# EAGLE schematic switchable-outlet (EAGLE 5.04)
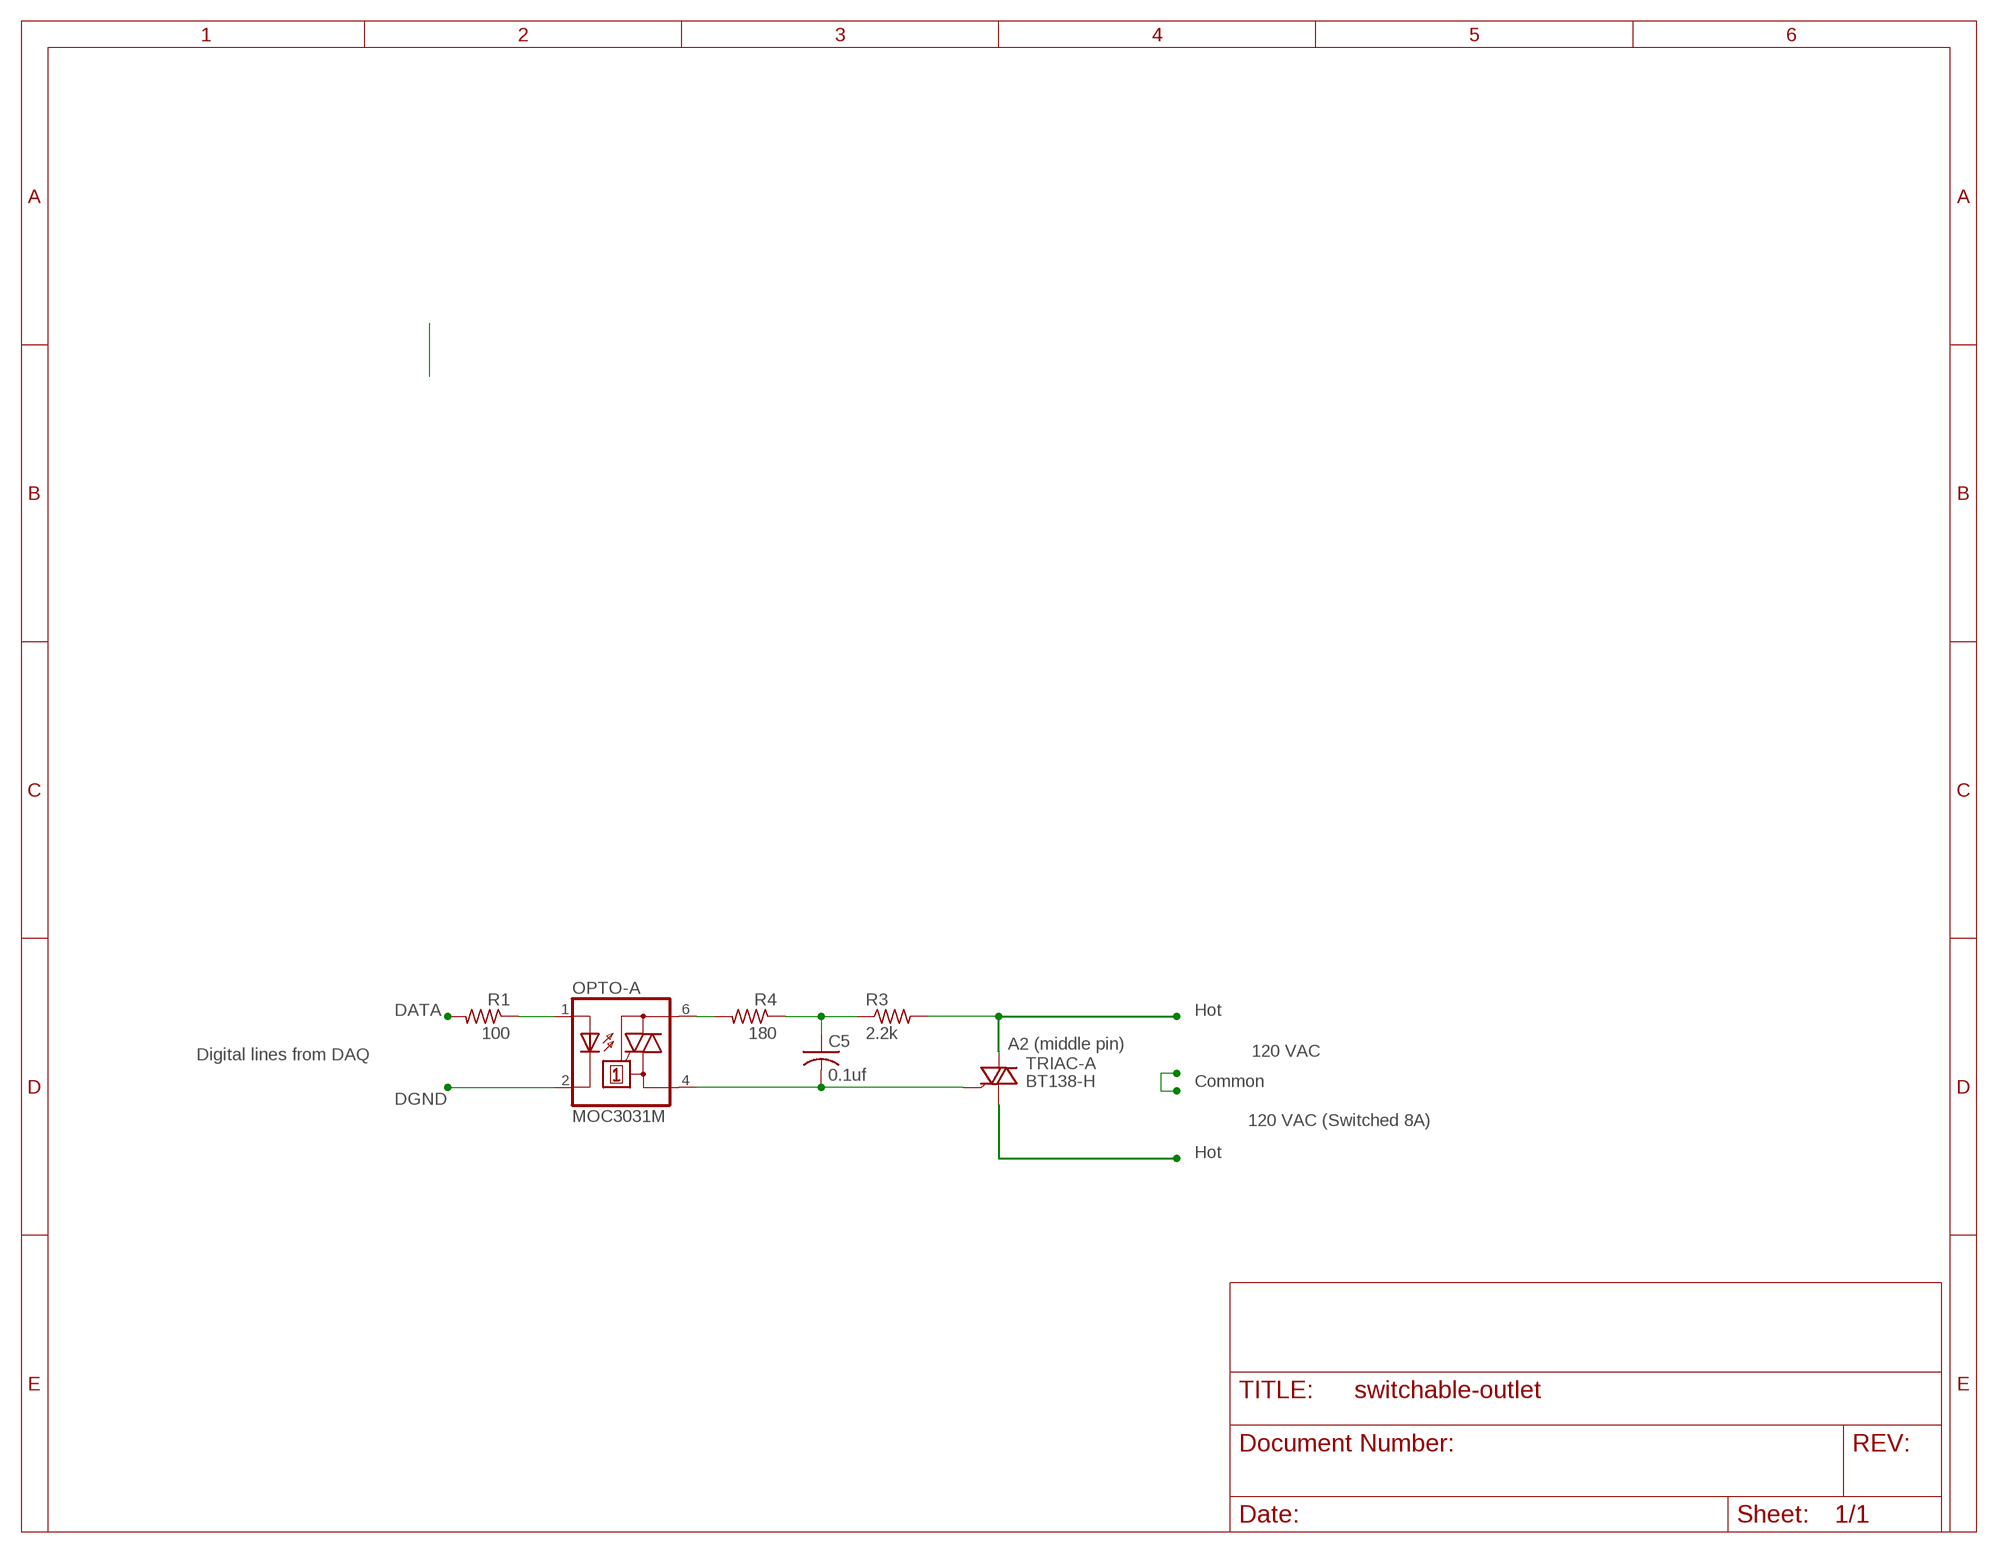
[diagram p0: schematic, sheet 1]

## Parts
C5  0.1uf  C-US050-035X075  [C050-035X075]
OPTO-A  MOC3031M  [DIL06]
R1  100  R-US_0204/5  [0204/5]
R3  2.2k  R-US_0204/5  [0204/5]
R4  180  R-US_0204/5  [0204/5]
TRIAC-A  BT138-H  [TO220BH]

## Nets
N$1: OPTO-A.2(C)
N$3: R1.2
N$13: OPTO-A.1(A) R1.1
N$14: OPTO-A.6(A2) R4.2
N$15: C5.1 R3.1 R4.1
N$16: R3.2 TRIAC-A.T1(A1) TRIAC-A.T2(A2)
N$17: C5.2 OPTO-A.4(A1) TRIAC-A.G

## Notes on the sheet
- DATA | Hot
- Digital lines from DAQ | A2 (middle pin)
- 120 VAC
- Common
- DGND
- 120 VAC (Switched 8A)
- Hot

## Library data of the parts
C5 = rcl:C-US: CAPACITOR, American symbol
OPTO-A = optocoupler:MOC30*: 6-Pin DIP Zero-Cross Optoisolators Triac Driver Output (250/400 Volt Peak) Source: http://www.fairchildsemi.com/ds/MO/MOC3043-M.pdf
R1 R3 R4 = resistor:R-US_: RESISTOR, American symbol
TRIAC-A = triac:BT138: TRIAC Source: http://www.semiconductors.philips.com BT138_SERIES_2.pdf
